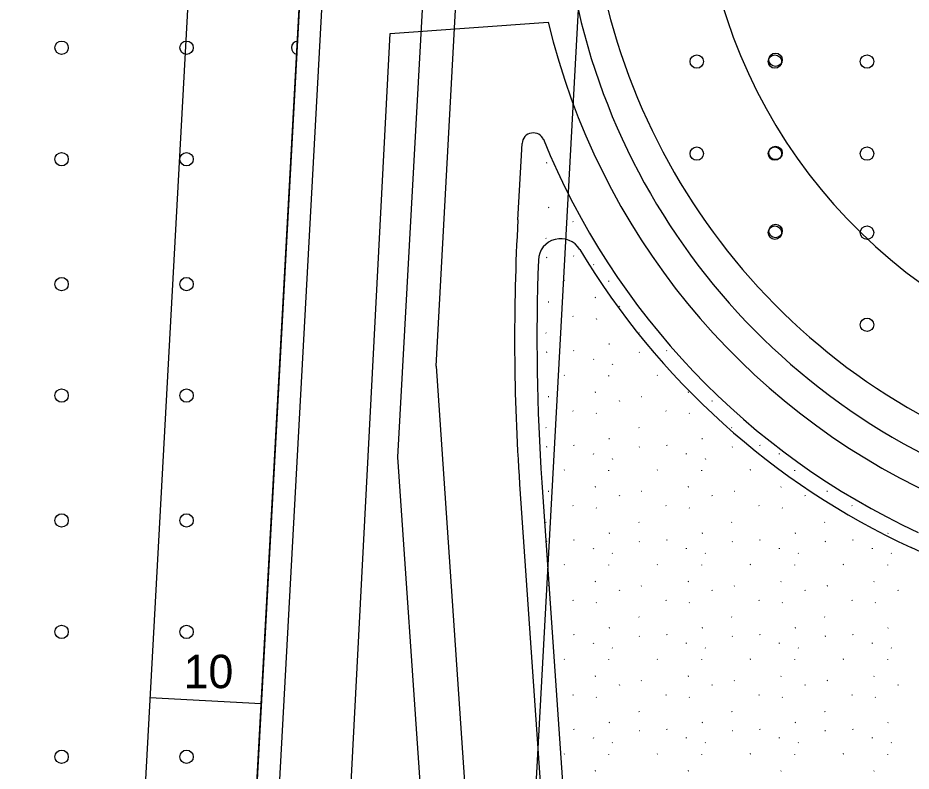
# Model space of a CAD drawing. Extents: x 419396 to 421519, y 4453567 to 4456767.
# Drawn here: x 420848.2 to 420928.3, y 4455272 to 4455339.6 of the extents above; entities that cross this region are included whole.
import ezdxf

# ---------------------------------------------------------------- set-up
doc = ezdxf.new("R2010")
doc.units = 0
for name, color, linetype in [('0_KADASTRO', 7, 'Continuous'), ('0_PLAN_ONAMA_İLAVE_SINIRI', 7, 'Continuous'), ('ADAKENARI1000', 7, 'Continuous'), ('F_YAPI_YAKLAŞMA', 7, 'Continuous'), ('KALDIRIM', 7, 'Continuous'), ('Level 33', 7, 'Continuous'), ('Level 41', 7, 'Continuous'), ('Level 62', 7, 'Continuous')]:
    doc.layers.add(name, color=color, linetype=linetype)

msp = doc.modelspace()

# ---------------------------------------------------------------- linework, layer by layer
at = {"layer": '0_KADASTRO'}
for points in [[(421128.218, 4455437.471), (421062.987, 4455307.75), (421022.211, 4455249.632), (420981.54, 4455191.664), (420919.088, 4455138.161), (420909.418, 4455143.046), (420905.841, 4455146.038), (420901.437, 4455149.953), (420897.849, 4455154.52), (420894.913, 4455159.74), (420892.303, 4455165.122), (420890.509, 4455172.625), (420889.849, 4455182.58), (420910.449, 4455560.119)], [(420652.359, 4454984.001), (420665.755, 4454988.47), (420707.293, 4455006.195), (420751.481, 4455032.994), (420769.069, 4455051.203), (420804.89, 4455072.7), (420840.78, 4455094.99), (420847.65, 4455100.22), (420853.39, 4455106.67), (420857.79, 4455114.1), (420861.99, 4455130.83), (420878.176, 4455427.467), (420710.4, 4455437.34), (420549.3, 4455446.81)]]:
    msp.add_lwpolyline(points, dxfattribs=at)
at = {"layer": '0_PLAN_ONAMA_İLAVE_SINIRI'}
msp.add_lwpolyline([(420876.648, 4455243.37), (420881.576, 4455338.189), (420895.76, 4455339.196)], dxfattribs=at)
msp.add_arc((420956.916, 4455353.76), 62.867, 193.39503, 245.10305, dxfattribs=at)
at = {"layer": 'ADAKENARI1000'}
msp.add_line((420878.176, 4455427.467), (420861.99, 4455130.83), dxfattribs=at)
msp.add_arc((420957.24, 4455354.621), 57.918, 176.87682, 245.10305, dxfattribs=at)
at = {"layer": 'F_YAPI_YAKLAŞMA'}
for p, q in [((420867.921, 4455423.062), (420852.057, 4455132.334)), ((420860.041, 4455278.646), (420870.026, 4455278.101))]:
    msp.add_line(p, q, dxfattribs=at)
msp.add_arc((420957.24, 4455354.621), 47.918, 176.87682, 245.10305, dxfattribs=at)
at = {"layer": 'KALDIRIM'}
for p, q in [((420885.695, 4455308.351), (420899.467, 4455560.744)), ((420880.173, 4455427.359), (420863.977, 4455130.529)), ((420889.159, 4455426.868), (420882.247, 4455300.18))]:
    msp.add_line(p, q, dxfattribs=at)
msp.add_arc((420956.916, 4455353.76), 60, 176.82754, 245.10305, dxfattribs=at)
at = {"layer": 'Level 33'}
for centre in [(420852.124, 4455336.917), (420863.325, 4455336.917), (420909.075, 4455335.679), (420916.075, 4455335.679), (420916.13, 4455335.83), (420924.332, 4455335.679), (420909.075, 4455327.415), (420916.075, 4455327.415), (420916.13, 4455327.478), (420924.332, 4455327.415), (420852.124, 4455326.917), (420863.325, 4455326.917), (420916.075, 4455320.327), (420916.13, 4455320.478), (420924.332, 4455320.327), (420852.124, 4455315.716), (420863.325, 4455315.716), (420924.332, 4455312.063), (420852.124, 4455305.716), (420863.325, 4455305.716), (420852.124, 4455294.515), (420863.325, 4455294.515), (420852.124, 4455284.515), (420863.325, 4455284.515), (420852.124, 4455273.314), (420863.325, 4455273.314)]:
    msp.add_circle(centre, 0.6, dxfattribs=at)
msp.add_arc((420873.325, 4455336.917), 0.6, 95.53022, 258.22337, dxfattribs=at)
at = {"layer": 'Level 41'}
for p, q in [((420895.613, 4455326.585), (420895.567, 4455326.562)), ((420897.223, 4455324.52), (420897.176, 4455324.497)), ((420895.796, 4455322.591), (420895.749, 4455322.568)), ((420897.968, 4455321.335), (420897.996, 4455321.291)), ((420895.532, 4455319.839), (420895.56, 4455319.795)), ((420895.613, 4455318.096), (420895.567, 4455318.073)), ((420898.022, 4455318.259), (420898.05, 4455318.216)), ((420899.822, 4455317.43), (420899.829, 4455317.482)), ((420901.495, 4455317.045), (420901.523, 4455317.001)), ((420897.223, 4455316.031), (420897.176, 4455316.008)), ((420901.188, 4455315.957), (420901.196, 4455316.008)), ((420899.987, 4455314.497), (420899.94, 4455314.474)), ((420895.796, 4455314.102), (420895.749, 4455314.079)), ((420902.102, 4455313.749), (420902.13, 4455313.705)), ((420897.968, 4455312.846), (420897.996, 4455312.802)), ((420900.057, 4455312.625), (420900.085, 4455312.582)), ((420895.532, 4455311.35), (420895.56, 4455311.306)), ((420903.864, 4455311.35), (420903.892, 4455311.306)), ((420901.243, 4455310.336), (420901.196, 4455310.313)), ((420895.613, 4455309.607), (420895.567, 4455309.584)), ((420898.022, 4455309.771), (420898.05, 4455309.727)), ((420903.946, 4455309.607), (420903.899, 4455309.584)), ((420906.354, 4455309.771), (420906.382, 4455309.727)), ((420899.822, 4455308.942), (420899.829, 4455308.993)), ((420901.495, 4455308.556), (420901.523, 4455308.512)), ((420897.223, 4455307.542), (420897.176, 4455307.519)), ((420901.188, 4455307.468), (420901.196, 4455307.519)), ((420905.555, 4455307.542), (420905.508, 4455307.519)), ((420895.796, 4455305.613), (420895.749, 4455305.59)), ((420899.987, 4455306.008), (420899.94, 4455305.985)), ((420904.128, 4455305.613), (420904.081, 4455305.59)), ((420908.319, 4455306.008), (420908.272, 4455305.985)), ((420902.102, 4455305.26), (420902.13, 4455305.217)), ((420910.434, 4455305.26), (420910.463, 4455305.217)), ((420897.968, 4455304.357), (420897.996, 4455304.313)), ((420900.057, 4455304.137), (420900.085, 4455304.093)), ((420906.3, 4455304.357), (420906.328, 4455304.313)), ((420908.389, 4455304.137), (420908.417, 4455304.093)), ((420895.532, 4455302.861), (420895.56, 4455302.817)), ((420903.864, 4455302.861), (420903.892, 4455302.817)), ((420912.196, 4455302.861), (420912.224, 4455302.817)), ((420901.243, 4455301.848), (420901.196, 4455301.825)), ((420909.575, 4455301.848), (420909.528, 4455301.825)), ((420895.613, 4455301.119), (420895.567, 4455301.096)), ((420898.022, 4455301.282), (420898.05, 4455301.238)), ((420903.946, 4455301.119), (420903.899, 4455301.096)), ((420906.354, 4455301.282), (420906.382, 4455301.238)), ((420912.278, 4455301.119), (420912.231, 4455301.096)), ((420914.686, 4455301.282), (420914.714, 4455301.238)), ((420899.822, 4455300.453), (420899.829, 4455300.504)), ((420901.495, 4455300.067), (420901.523, 4455300.023)), ((420908.154, 4455300.453), (420908.161, 4455300.504)), ((420909.827, 4455300.067), (420909.855, 4455300.023)), ((420916.486, 4455300.453), (420916.493, 4455300.504)), ((420897.223, 4455299.054), (420897.176, 4455299.031)), ((420901.188, 4455298.979), (420901.196, 4455299.031)), ((420905.555, 4455299.054), (420905.508, 4455299.031)), ((420909.52, 4455298.979), (420909.528, 4455299.031)), ((420913.887, 4455299.054), (420913.841, 4455299.031)), ((420917.853, 4455298.979), (420917.86, 4455299.031)), ((420899.987, 4455297.519), (420899.94, 4455297.497)), ((420908.319, 4455297.519), (420908.272, 4455297.497)), ((420916.651, 4455297.519), (420916.604, 4455297.497)), ((420895.796, 4455297.124), (420895.749, 4455297.102)), ((420902.102, 4455296.772), (420902.13, 4455296.728)), ((420904.128, 4455297.124), (420904.081, 4455297.102)), ((420910.434, 4455296.772), (420910.463, 4455296.728)), ((420912.46, 4455297.124), (420912.413, 4455297.102)), ((420918.767, 4455296.772), (420918.795, 4455296.728)), ((420920.792, 4455297.124), (420920.745, 4455297.102)), ((420897.968, 4455295.868), (420897.996, 4455295.825)), ((420900.057, 4455295.648), (420900.085, 4455295.604)), ((420906.3, 4455295.868), (420906.328, 4455295.825)), ((420908.389, 4455295.648), (420908.417, 4455295.604)), ((420914.632, 4455295.868), (420914.66, 4455295.825)), ((420916.721, 4455295.648), (420916.749, 4455295.604)), ((420922.964, 4455295.868), (420922.992, 4455295.825)), ((420895.532, 4455294.372), (420895.56, 4455294.329)), ((420903.864, 4455294.372), (420903.892, 4455294.329)), ((420912.196, 4455294.372), (420912.224, 4455294.329)), ((420920.528, 4455294.372), (420920.556, 4455294.329)), ((420898.022, 4455292.793), (420898.05, 4455292.749)), ((420901.243, 4455293.359), (420901.196, 4455293.336)), ((420906.354, 4455292.793), (420906.382, 4455292.749)), ((420909.575, 4455293.359), (420909.528, 4455293.336)), ((420914.686, 4455292.793), (420914.714, 4455292.749)), ((420917.907, 4455293.359), (420917.86, 4455293.336)), ((420923.019, 4455292.793), (420923.047, 4455292.749)), ((420926.239, 4455293.359), (420926.192, 4455293.336)), ((420895.613, 4455292.63), (420895.567, 4455292.607)), ((420899.822, 4455291.964), (420899.829, 4455292.015)), ((420903.946, 4455292.63), (420903.899, 4455292.607)), ((420908.154, 4455291.964), (420908.161, 4455292.015)), ((420912.278, 4455292.63), (420912.231, 4455292.607)), ((420916.486, 4455291.964), (420916.493, 4455292.015)), ((420920.61, 4455292.63), (420920.563, 4455292.607)), ((420924.818, 4455291.964), (420924.826, 4455292.015)), ((420901.495, 4455291.578), (420901.523, 4455291.535)), ((420909.827, 4455291.578), (420909.855, 4455291.535)), ((420918.159, 4455291.578), (420918.187, 4455291.535)), ((420926.492, 4455291.578), (420926.52, 4455291.535)), ((420897.223, 4455290.565), (420897.176, 4455290.542)), ((420901.188, 4455290.491), (420901.196, 4455290.542)), ((420905.555, 4455290.565), (420905.508, 4455290.542)), ((420909.52, 4455290.491), (420909.528, 4455290.542)), ((420913.887, 4455290.565), (420913.841, 4455290.542)), ((420917.853, 4455290.491), (420917.86, 4455290.542)), ((420922.22, 4455290.565), (420922.173, 4455290.542)), ((420926.185, 4455290.491), (420926.192, 4455290.542)), ((420899.987, 4455289.031), (420899.94, 4455289.008)), ((420908.319, 4455289.031), (420908.272, 4455289.008)), ((420916.651, 4455289.031), (420916.604, 4455289.008)), ((420924.983, 4455289.031), (420924.936, 4455289.008)), ((420895.796, 4455288.636), (420895.749, 4455288.613)), ((420902.102, 4455288.283), (420902.13, 4455288.239)), ((420904.128, 4455288.636), (420904.081, 4455288.613)), ((420910.434, 4455288.283), (420910.463, 4455288.239)), ((420912.46, 4455288.636), (420912.413, 4455288.613)), ((420918.767, 4455288.283), (420918.795, 4455288.239)), ((420920.792, 4455288.636), (420920.745, 4455288.613)), ((420927.099, 4455288.283), (420927.127, 4455288.239)), ((420897.968, 4455287.379), (420897.996, 4455287.336)), ((420900.057, 4455287.159), (420900.085, 4455287.115)), ((420906.3, 4455287.379), (420906.328, 4455287.336)), ((420908.389, 4455287.159), (420908.417, 4455287.115)), ((420914.632, 4455287.379), (420914.66, 4455287.336)), ((420916.721, 4455287.159), (420916.749, 4455287.115)), ((420922.964, 4455287.379), (420922.992, 4455287.336)), ((420925.053, 4455287.159), (420925.081, 4455287.115)), ((420903.864, 4455285.883), (420903.892, 4455285.84)), ((420912.196, 4455285.883), (420912.224, 4455285.84)), ((420920.528, 4455285.883), (420920.556, 4455285.84)), ((420901.243, 4455284.87), (420901.196, 4455284.847)), ((420909.575, 4455284.87), (420909.528, 4455284.847)), ((420917.907, 4455284.87), (420917.86, 4455284.847)), ((420926.239, 4455284.87), (420926.192, 4455284.847)), ((420898.022, 4455284.304), (420898.05, 4455284.261)), ((420903.946, 4455284.141), (420903.899, 4455284.118)), ((420906.354, 4455284.304), (420906.382, 4455284.261)), ((420912.278, 4455284.141), (420912.231, 4455284.118)), ((420914.686, 4455284.304), (420914.714, 4455284.261)), ((420920.61, 4455284.141), (420920.563, 4455284.118)), ((420923.019, 4455284.304), (420923.047, 4455284.261)), ((420899.822, 4455283.475), (420899.829, 4455283.526)), ((420901.495, 4455283.089), (420901.523, 4455283.046)), ((420908.154, 4455283.475), (420908.161, 4455283.526)), ((420909.827, 4455283.089), (420909.855, 4455283.046)), ((420916.486, 4455283.475), (420916.493, 4455283.526)), ((420918.159, 4455283.089), (420918.187, 4455283.046)), ((420924.818, 4455283.475), (420924.826, 4455283.526)), ((420926.492, 4455283.089), (420926.52, 4455283.046)), ((420897.223, 4455282.076), (420897.176, 4455282.053)), ((420901.188, 4455282.002), (420901.196, 4455282.053)), ((420905.555, 4455282.076), (420905.508, 4455282.053)), ((420909.52, 4455282.002), (420909.528, 4455282.053)), ((420913.887, 4455282.076), (420913.841, 4455282.053)), ((420917.853, 4455282.002), (420917.86, 4455282.053)), ((420922.22, 4455282.076), (420922.173, 4455282.053)), ((420926.185, 4455282.002), (420926.192, 4455282.053)), ((420899.987, 4455280.542), (420899.94, 4455280.519)), ((420904.128, 4455280.147), (420904.081, 4455280.124)), ((420908.319, 4455280.542), (420908.272, 4455280.519)), ((420912.46, 4455280.147), (420912.413, 4455280.124)), ((420916.651, 4455280.542), (420916.604, 4455280.519)), ((420920.792, 4455280.147), (420920.745, 4455280.124)), ((420924.983, 4455280.542), (420924.936, 4455280.519)), ((420902.102, 4455279.794), (420902.13, 4455279.75)), ((420910.434, 4455279.794), (420910.463, 4455279.75)), ((420918.767, 4455279.794), (420918.795, 4455279.75)), ((420927.099, 4455279.794), (420927.127, 4455279.75)), ((420897.968, 4455278.891), (420897.996, 4455278.847)), ((420900.057, 4455278.67), (420900.085, 4455278.626)), ((420906.3, 4455278.891), (420906.328, 4455278.847)), ((420908.389, 4455278.67), (420908.417, 4455278.626)), ((420914.632, 4455278.891), (420914.66, 4455278.847)), ((420916.721, 4455278.67), (420916.749, 4455278.626)), ((420922.964, 4455278.891), (420922.992, 4455278.847)), ((420925.053, 4455278.67), (420925.081, 4455278.626)), ((420903.864, 4455277.395), (420903.892, 4455277.351)), ((420912.196, 4455277.395), (420912.224, 4455277.351)), ((420920.528, 4455277.395), (420920.556, 4455277.351)), ((420901.243, 4455276.381), (420901.196, 4455276.358)), ((420909.575, 4455276.381), (420909.528, 4455276.358)), ((420917.907, 4455276.381), (420917.86, 4455276.358)), ((420926.239, 4455276.381), (420926.192, 4455276.358)), ((420898.022, 4455275.815), (420898.05, 4455275.772)), ((420903.946, 4455275.652), (420903.899, 4455275.629)), ((420906.354, 4455275.815), (420906.382, 4455275.772)), ((420912.278, 4455275.652), (420912.231, 4455275.629)), ((420914.686, 4455275.815), (420914.714, 4455275.772)), ((420920.61, 4455275.652), (420920.563, 4455275.629)), ((420923.019, 4455275.815), (420923.047, 4455275.772)), ((420899.822, 4455274.986), (420899.829, 4455275.038)), ((420901.495, 4455274.601), (420901.523, 4455274.557)), ((420908.154, 4455274.986), (420908.161, 4455275.038)), ((420909.827, 4455274.601), (420909.855, 4455274.557)), ((420916.486, 4455274.986), (420916.493, 4455275.038)), ((420918.159, 4455274.601), (420918.187, 4455274.557)), ((420924.818, 4455274.986), (420924.826, 4455275.038)), ((420926.492, 4455274.601), (420926.52, 4455274.557)), ((420897.223, 4455273.587), (420897.176, 4455273.564)), ((420901.188, 4455273.513), (420901.196, 4455273.564)), ((420905.555, 4455273.587), (420905.508, 4455273.564)), ((420909.52, 4455273.513), (420909.528, 4455273.564)), ((420913.887, 4455273.587), (420913.841, 4455273.564)), ((420917.853, 4455273.513), (420917.86, 4455273.564)), ((420922.22, 4455273.587), (420922.173, 4455273.564)), ((420926.185, 4455273.513), (420926.192, 4455273.564)), ((420899.987, 4455272.053), (420899.94, 4455272.03)), ((420908.319, 4455272.053), (420908.272, 4455272.03)), ((420916.651, 4455272.053), (420916.604, 4455272.03)), ((420924.983, 4455272.053), (420924.936, 4455272.03))]:
    msp.add_line(p, q, dxfattribs=at)
at = {"layer": 'Level 62'}
for p, q in [((420893.031, 4455321.463), (420893.412, 4455328.334)), ((420885.695, 4455308.351), (420892.964, 4455202.466)), ((420882.247, 4455300.18), (420888.974, 4455202.192)), ((420893.187, 4455297.78), (420897.086, 4455240.979)), ((420895.182, 4455297.917), (420899.082, 4455241.116)), ((420960.76, 4455277.008), (420928.289, 4455292.079))]:
    msp.add_line(p, q, dxfattribs=at)
for centre, radius, start, end in [((420894.41, 4455328.279), 1, 22.17828, 176.82754), ((420956.916, 4455353.76), 66.5, 202.13725, 245.10305), ((421083.988, 4455310.879), 191.25, 176.82754, 183.92722), ((420896.865, 4455317.789), 2, 30.92189, 177.88523), ((420956.916, 4455353.76), 68, 210.92189, 245.10305), ((421083.988, 4455310.879), 189.25, 177.88523, 183.92722)]:
    msp.add_arc(centre, radius, start, end, dxfattribs=at)

# ---------------------------------------------------------------- texts
at = {"layer": 'F_YAPI_YAKLAŞMA'}
msp.add_text('10', height=3, dxfattribs=at).set_placement((420863.058, 4455279.468))

doc.saveas('drawing.dxf')
